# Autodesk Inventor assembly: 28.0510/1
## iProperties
Created: 2007-06
Part Number: 28.0510/1
Document SubType Name: Assembly
Designer: Andy Moles
Description: TIMING BELT PULLEY LR 6  10mm
Author: Andy Moles
